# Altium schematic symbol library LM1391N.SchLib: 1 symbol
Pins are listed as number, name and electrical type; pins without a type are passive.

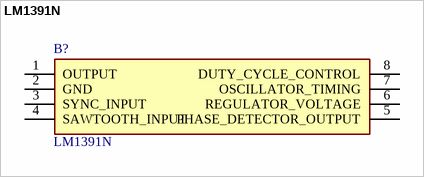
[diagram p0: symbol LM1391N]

## LM1391N
designator B?
IC PHASE-LOCKED LOOP 8DIP; Manufacturer_Name: Texas Instruments; Geometry.Height: 5.08mm
footprint DIP787W53P254L982H508Q8N
pins: 1 OUTPUT, 2 GND, 3 SYNC_INPUT, 4 SAWTOOTH_INPUT, 5 PHASE_DETECTOR_OUTPUT, 6 REGULATOR_VOLTAGE, 7 OSCILLATOR_TIMING, 8 DUTY_CYCLE_CONTROL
